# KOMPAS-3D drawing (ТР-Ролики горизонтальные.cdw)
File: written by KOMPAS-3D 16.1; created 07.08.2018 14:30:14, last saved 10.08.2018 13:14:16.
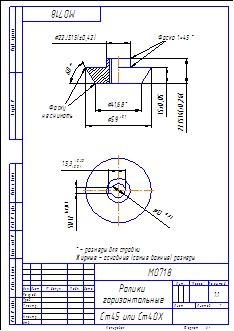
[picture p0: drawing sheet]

Sheet 1: A4, portrait

Title block, sheet 1: name: Ролики / горизонтальные; designation: М0718; material: Ст45 или Ст40Х; scale: 1:1; sheets: 1; sheet format: A4; stored path: C:\Users\User\Desktop\Станки\Малый 0718\ТР-Ролики горизонтальные.cdw

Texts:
  User
  JS15( 0,42)
  JS15
  JS14( 0,26)
  Фаску
  не снимать
  Фаска 1 45
  * - размеры для справки
  Жирные - основные (самые важные) размеры
Dimensions and other numbers on the sheet: 15; 41,68; 59; 22; 23; 13; 15,3; 5; 1:1; 1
